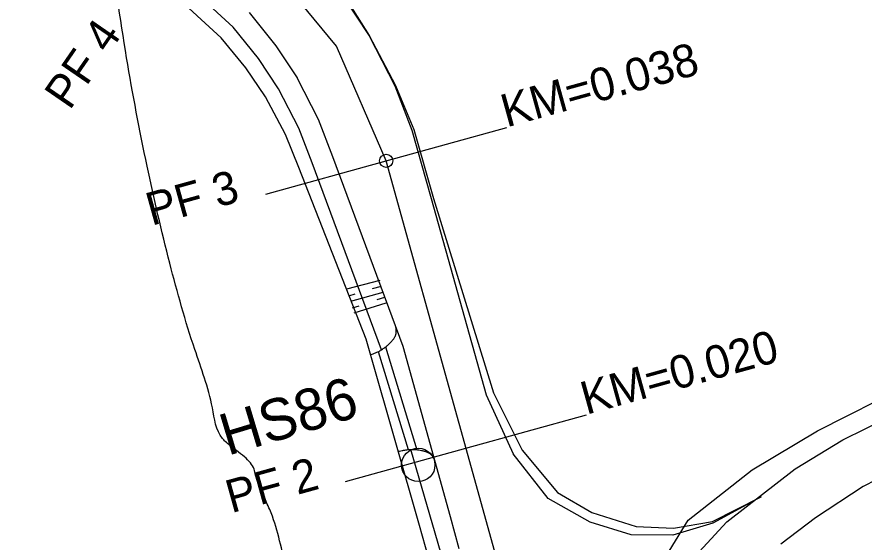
# Model space of a CAD drawing. Extents: x -478102 to -473059, y -1117705 to -1114104.
# Drawn here: x -476287.7 to -476236.8, y -1117086.7 to -1117055.2 of the extents above; entities that cross this region are included whole.
import ezdxf

# ---------------------------------------------------------------- set-up
doc = ezdxf.new("R2010")
doc.units = 0
for name, color, linetype in [('BodoveZnackySachtaKanalizacni', 7, 'Continuous'), ('cestn___p____kop', 7, 'Continuous'), ('cesty', 7, 'Continuous'), ('POLYGONY_SITUACE_PF', 7, 'Continuous'), ('POLYGONY_SITUACE_PF_POPISY', 7, 'Continuous'), ('POLYGONY_SITUACE_PO', 7, 'Continuous'), ('popis', 7, 'Continuous'), ('RozhraniKultur', 7, 'Continuous'), ('RozhraniVozovky', 7, 'Continuous'), ('TP_HS', 7, 'Continuous'), ('Vrstevnice_hlavni', 7, 'Continuous'), ('Vrstevnice_vedlejsi', 7, 'Continuous')]:
    doc.layers.add(name, color=color, linetype=linetype)

msp = doc.modelspace()

# ---------------------------------------------------------------- linework, layer by layer
at = {"layer": 'BodoveZnackySachtaKanalizacni'}
msp.add_circle((-476263.594, -1117082.052), 1, dxfattribs=at)
at = {"layer": 'cestn___p____kop'}
for p, q in [((-476265.9, -1117070.991), (-476267.895, -1117071.51)), ((-476265.814, -1117071.337), (-476266.354, -1117071.489)), ((-476267.765, -1117071.892), (-476267.384, -1117071.791)), ((-476265.713, -1117071.698), (-476267.664, -1117072.238)), ((-476265.533, -1117072.346), (-476267.456, -1117072.937)), ((-476265.626, -1117072.007), (-476266.087, -1117072.144)), ((-476267.549, -1117072.613), (-476267.146, -1117072.497))]:
    msp.add_line(p, q, dxfattribs=at)
at = {"layer": 'cesty'}
for p, q in [((-476274.708, -1117055.766), (-476277.732, -1117052.983)), ((-476268.093, -1117053.939), (-476266.552, -1117056.287)), ((-476268.033, -1117053.896), (-476266.535, -1117056.277)), ((-476273.752, -1117054.898), (-476272.135, -1117056.886)), ((-476273.179, -1117057.645), (-476274.708, -1117055.766)), ((-476266.552, -1117056.287), (-476265.008, -1117059.295)), ((-476266.535, -1117056.277), (-476264.959, -1117059.274)), ((-476272.135, -1117056.886), (-476270.863, -1117058.822)), ((-476271.976, -1117059.478), (-476273.179, -1117057.645)), ((-476269.578, -1117061.325), (-476270.863, -1117058.822)), ((-476270.762, -1117061.842), (-476271.976, -1117059.478)), ((-476268.718, -1117063.566), (-476269.578, -1117061.325)), ((-476269.962, -1117063.926), (-476270.762, -1117061.842)), ((-476264.504, -1117074.94), (-476268.718, -1117063.566)), ((-476265.802, -1117075.139), (-476269.962, -1117063.926)), ((-476262.821, -1117066.053), (-476259.518, -1117077.845)), ((-476262.685, -1117066.063), (-476259.083, -1117077.725)), ((-476261.667, -1117085.17), (-476264.504, -1117074.94)), ((-476259.518, -1117077.845), (-476257.901, -1117081.393)), ((-476259.083, -1117077.725), (-476257.353, -1117081.16)), ((-476258.59, -1117099.803), (-476264.043, -1117081.125)), ((-476255.801, -1117084.079), (-476257.901, -1117081.393)), ((-476257.353, -1117081.16), (-476255.233, -1117083.7)), ((-476255.233, -1117083.7), (-476253.179, -1117084.916)), ((-476245.946, -1117085.453), (-476243.022, -1117083.979)), ((-476243.022, -1117083.979), (-476245.917, -1117085.558)), ((-476243.022, -1117083.979), (-476243.022, -1117083.979)), ((-476253.277, -1117085.498), (-476255.801, -1117084.079)), ((-476253.179, -1117084.916), (-476250.53, -1117085.755)), ((-476261.133, -1117087.098), (-476261.667, -1117085.17)), ((-476250.826, -1117086.249), (-476253.277, -1117085.498)), ((-476253.277, -1117085.498), (-476253.277, -1117085.498)), ((-476245.917, -1117085.558), (-476248.318, -1117086.272)), ((-476248.281, -1117085.855), (-476245.946, -1117085.453)), ((-476250.53, -1117085.755), (-476248.281, -1117085.855)), ((-476248.318, -1117086.272), (-476250.826, -1117086.249))]:
    msp.add_line(p, q, dxfattribs=at)
for points in [[(-476266.732, -1117074.511), (-476270.768, -1117064.204), (-476271.566, -1117062.212), (-476272.761, -1117059.954), (-476273.936, -1117058.207), (-476275.415, -1117056.411), (-476278.317, -1117053.74), (-476280.366, -1117052.325), (-476282.34, -1117051.259), (-476283.992, -1117050.544), (-476285.595, -1117050.022), (-476288.167, -1117049.481), (-476290.873, -1117049.234), (-476293.603, -1117049.34), (-476293.603, -1117049.34), (-476299.076, -1117049.264)], [(-476265.008, -1117059.295), (-476263.985, -1117061.96), (-476262.821, -1117066.053)], [(-476264.959, -1117059.274), (-476263.868, -1117061.922), (-476262.685, -1117066.063)], [(-476266.45, -1117075.48), (-476266.732, -1117074.511)], [(-476263.521, -1117085.684), (-476266.45, -1117075.48)], [(-476262.981, -1117087.61), (-476263.521, -1117085.684)]]:
    msp.add_lwpolyline(points, dxfattribs=at)
at = {"layer": 'POLYGONY_SITUACE_PF'}
for points in [[(-476272.745, -1117065.801), (-476265.518, -1117063.797), (-476258.29, -1117061.793)], [(-476267.961, -1117083.054), (-476260.734, -1117081.05), (-476253.507, -1117079.047)]]:
    msp.add_lwpolyline(points, dxfattribs=at)
at = {"layer": 'POLYGONY_SITUACE_PO'}
msp.add_lwpolyline([(-476250.954, -1117100.054), (-476256.772, -1117095.342), (-476265.518, -1117063.797), (-476268.51, -1117056.912), (-476273.282, -1117051.116), (-476279.465, -1117046.859), (-476286.581, -1117044.469), (-476294.08, -1117044.131), (-476301.427, -1117045.065)], dxfattribs=at)
msp.add_circle((-476265.518, -1117063.797), 0.395, dxfattribs=at)
at = {"layer": 'RozhraniKultur'}
msp.add_lwpolyline([(-476326.155, -1117118.092), (-476289.536, -1117114.347), (-476268.698, -1117113.377), (-476254.616, -1117112.232), (-476253.368, -1117111.396), (-476254.26, -1117105.118), (-476253.444, -1117098.834), (-476252.052, -1117092.56), (-476249.674, -1117089.102), (-476247.41, -1117085.365), (-476243.552, -1117082.341), (-476239.642, -1117080.005), (-476234.251, -1117077.288), (-476223.428, -1117073.653), (-476215.212, -1117070.499), (-476211.753, -1117068.101), (-476207.257, -1117063.687), (-476203.922, -1117059.007), (-476201.245, -1117053.431), (-476199.908, -1117046.384), (-476198.206, -1117031.932)], dxfattribs=at)
at = {"layer": 'RozhraniVozovky'}
for points in [[(-476247.93, -1117088.545), (-476245.077, -1117085.472), (-476240.982, -1117082.296), (-476238.115, -1117080.557), (-476233.979, -1117078.501), (-476225.492, -1117075.329), (-476219.895, -1117073.227), (-476215.189, -1117071.158), (-476211.766, -1117069.21), (-476209.272, -1117067.263), (-476206.779, -1117064.716), (-476204.692, -1117061.981), (-476203, -1117058.967), (-476200.833, -1117053.375), (-476199.75, -1117048.873), (-476198.727, -1117040.3), (-476198.206, -1117031.932), (-476198.165, -1117024.787), (-476198.499, -1117019.299), (-476199.36, -1117013.806), (-476200.192, -1117009.793)], [(-476196.364, -1117012.13), (-476195.729, -1117017.189), (-476195.176, -1117023.395), (-476195.112, -1117027.233), (-476195.235, -1117031.513), (-476195.559, -1117037.637), (-476196.033, -1117043.394), (-476196.483, -1117047.979), (-476197.306, -1117052.252), (-476198.582, -1117056.674), (-476200.039, -1117060.081), (-476202.244, -1117063.965), (-476204.836, -1117067.407), (-476207.857, -1117070.218), (-476210.834, -1117072.302), (-476213.828, -1117073.953), (-476223.737, -1117077.95), (-476233.774, -1117081.756), (-476236.901, -1117083.35), (-476239.761, -1117085.24), (-476241.85, -1117086.802)]]:
    msp.add_lwpolyline(points, dxfattribs=at)
at = {"layer": 'TP_HS'}
for p, q in [((-476265.993, -1117075.246), (-476264.198, -1117081.134)), ((-476265.554, -1117074.971), (-476263.674, -1117081.139))]:
    msp.add_line(p, q, dxfattribs=at)
for points in [[(-476266.459, -1117075.447), (-476266.37, -1117075.412), (-476266.227, -1117075.352), (-476266.085, -1117075.289), (-476265.969, -1117075.234), (-476265.857, -1117075.172), (-476265.748, -1117075.106), (-476265.694, -1117075.07), (-476265.641, -1117075.034), (-476265.509, -1117074.935), (-476265.386, -1117074.827), (-476265.269, -1117074.711), (-476265.212, -1117074.65), (-476265.156, -1117074.588), (-476265.096, -1117074.517), (-476265.043, -1117074.443), (-476264.998, -1117074.365), (-476264.978, -1117074.323), (-476264.961, -1117074.279), (-476264.939, -1117074.212), (-476264.931, -1117074.177), (-476264.924, -1117074.142), (-476264.917, -1117074.074), (-476264.918, -1117074.005), (-476264.936, -1117073.778)], [(-476264.797, -1117081.237), (-476264.713, -1117081.218), (-476264.561, -1117081.188), (-476264.484, -1117081.174), (-476264.408, -1117081.161), (-476264.281, -1117081.142), (-476264.154, -1117081.131), (-476264.026, -1117081.125), (-476263.962, -1117081.124), (-476263.897, -1117081.124), (-476263.732, -1117081.133), (-476263.569, -1117081.154), (-476263.408, -1117081.185), (-476263.327, -1117081.203), (-476263.245, -1117081.224), (-476263.156, -1117081.249), (-476263.071, -1117081.281), (-476262.989, -1117081.321), (-476262.95, -1117081.344), (-476262.911, -1117081.371), (-476262.856, -1117081.415), (-476262.829, -1117081.439), (-476262.805, -1117081.464), (-476262.782, -1117081.49), (-476262.761, -1117081.517), (-476262.723, -1117081.575), (-476262.611, -1117081.773)]]:
    msp.add_spline(points, degree=3, dxfattribs=at)
at = {"layer": 'Vrstevnice_hlavni'}
msp.add_spline([(-476249.493, -1117108.392), (-476249.775, -1117107.699), (-476250.264, -1117106.97), (-476250.958, -1117106.207), (-476251.857, -1117105.408), (-476252.513, -1117105.14), (-476252.925, -1117105.402), (-476253.095, -1117106.195), (-476253.235, -1117107.1), (-476253.347, -1117108.118), (-476253.43, -1117109.248), (-476253.596, -1117109.985), (-476253.847, -1117110.328), (-476254.181, -1117110.278), (-476255.528, -1117110.336), (-476257.887, -1117110.502), (-476261.259, -1117110.776), (-476263.654, -1117110.928), (-476265.074, -1117110.957), (-476265.519, -1117110.863), (-476266.5, -1117108.002), (-476268.017, -1117102.375), (-476270.071, -1117093.98), (-476271.569, -1117088.098), (-476272.511, -1117084.73), (-476272.897, -1117083.874), (-476273.181, -1117083.184), (-476273.365, -1117082.66), (-476273.447, -1117082.301), (-476273.665, -1117081.937), (-476274.021, -1117081.569), (-476274.513, -1117081.196), (-476274.898, -1117080.887), (-476275.174, -1117080.644), (-476275.342, -1117080.466), (-476275.953, -1117078.624), (-476277.006, -1117075.118), (-476278.503, -1117069.948), (-476279.866, -1117064.113), (-476281.094, -1117057.612), (-476282.188, -1117050.447), (-476282.997, -1117045.306), (-476283.52, -1117042.188), (-476283.758, -1117041.094), (-476283.99, -1117040.218), (-476284.216, -1117039.561), (-476284.654, -1117038.684)], degree=3, dxfattribs=at)
at = {"layer": 'Vrstevnice_vedlejsi'}
for points in [[(-476361.641, -1116910.017), (-476360.991, -1116911.137), (-476360.552, -1116912.67), (-476360.323, -1116914.616), (-476360.306, -1116916.973), (-476360.308, -1116918.585), (-476360.329, -1116919.449), (-476360.369, -1116919.567), (-476360.386, -1116919.663), (-476360.38, -1116919.738), (-476360.35, -1116919.79), (-476360.486, -1116921.699), (-476360.787, -1116925.464), (-476361.254, -1116931.086), (-476361.67, -1116935.051), (-476362.037, -1116937.36), (-476362.353, -1116938.012), (-476362.549, -1116938.736), (-476362.623, -1116939.532), (-476362.576, -1116940.398), (-476362.264, -1116942.869), (-476361.686, -1116946.945), (-476360.843, -1116952.626), (-476360.093, -1116958.73), (-476359.435, -1116965.256), (-476358.871, -1116972.204), (-476358.36, -1116977.092), (-476357.904, -1116979.919), (-476357.501, -1116980.685), (-476356.57, -1116984.99), (-476355.11, -1116992.835), (-476353.122, -1117004.219), (-476351.571, -1117012.905), (-476350.455, -1117018.893), (-476349.776, -1117022.183), (-476349.504, -1117027.698), (-476349.639, -1117035.437), (-476350.182, -1117045.4), (-476350.307, -1117053.191), (-476350.012, -1117058.811), (-476349.298, -1117062.259), (-476350.091, -1117065.67), (-476352.39, -1117069.042), (-476356.195, -1117072.377), (-476359.92, -1117076.705), (-476363.566, -1117082.026), (-476367.131, -1117088.339), (-476371.33, -1117094.641), (-476376.164, -1117100.933), (-476381.631, -1117107.213), (-476386.474, -1117112.181), (-476390.692, -1117115.834), (-476394.286, -1117118.174), (-476397.491, -1117120.393), (-476400.306, -1117122.492), (-476402.732, -1117124.472), (-476402.928, -1117127.738), (-476400.894, -1117132.291), (-476396.631, -1117138.131), (-476389.647, -1117141.585), (-476379.944, -1117142.653), (-476367.521, -1117141.334), (-476355.525, -1117141.406), (-476343.957, -1117142.868), (-476332.816, -1117145.722), (-476324.482, -1117147.814), (-476318.952, -1117149.144), (-476316.229, -1117149.714), (-476310.745, -1117150.91), (-476302.502, -1117152.733), (-476291.498, -1117155.183), (-476284.107, -1117156.821), (-476280.33, -1117157.647), (-476280.165, -1117157.662), (-476279.816, -1117157.743), (-476279.284, -1117157.891), (-476278.569, -1117158.106), (-476278.072, -1117158.306), (-476277.796, -1117158.489), (-476277.739, -1117158.657), (-476277.684, -1117158.815), (-476277.629, -1117158.963), (-476277.576, -1117159.102), (-476277.523, -1117159.234), (-476277.472, -1117159.361), (-476277.423, -1117159.482), (-476277.379, -1117159.591), (-476277.34, -1117159.689), (-476277.307, -1117159.775), (-476277.275, -1117159.863), (-476277.243, -1117159.954), (-476277.212, -1117160.046), (-476277.173, -1117160.139), (-476277.129, -1117160.233), (-476277.078, -1117160.326), (-476277.04, -1117160.421), (-476277.015, -1117160.516)], [(-476223.981, -1117207.237), (-476224.285, -1117206.855), (-476224.501, -1117206.557), (-476224.628, -1117206.343), (-476224.668, -1117206.213), (-476224.801, -1117205.902), (-476225.026, -1117205.411), (-476225.345, -1117204.739), (-476225.578, -1117204.261), (-476225.727, -1117203.975), (-476225.791, -1117203.883), (-476225.875, -1117203.662), (-476225.98, -1117203.311), (-476226.105, -1117202.831), (-476226.229, -1117202.417), (-476226.352, -1117202.067), (-476226.475, -1117201.782), (-476226.572, -1117201.501), (-476226.643, -1117201.224), (-476226.689, -1117200.951), (-476227.057, -1117200.755), (-476227.747, -1117200.637), (-476228.759, -1117200.595), (-476229.446, -1117200.566), (-476229.808, -1117200.548), (-476229.845, -1117200.544), (-476229.875, -1117200.547), (-476229.898, -1117200.559), (-476229.914, -1117200.578), (-476229.923, -1117200.586), (-476229.927, -1117200.583), (-476229.925, -1117200.567), (-476229.926, -1117200.55), (-476229.93, -1117200.533), (-476229.937, -1117200.515), (-476230.309, -1117199.985), (-476231.045, -1117198.942), (-476232.146, -1117197.387), (-476233.138, -1117195.885), (-476234.022, -1117194.438), (-476234.797, -1117193.044), (-476236.35, -1117190.18), (-476238.683, -1117185.847), (-476241.794, -1117180.043), (-476244.171, -1117175.438), (-476245.814, -1117172.033), (-476246.723, -1117169.826), (-476247.372, -1117168.01), (-476247.761, -1117166.585), (-476247.891, -1117165.55), (-476248.161, -1117164.525), (-476248.57, -1117163.508), (-476249.119, -1117162.501), (-476249.598, -1117161.498), (-476250.007, -1117160.498), (-476250.346, -1117159.503), (-476250.69, -1117158.53), (-476251.038, -1117157.58), (-476251.39, -1117156.652), (-476251.803, -1117155.599), (-476252.277, -1117154.423), (-476252.812, -1117153.123), (-476253.36, -1117151.76), (-476253.922, -1117150.336), (-476254.497, -1117148.85), (-476255.085, -1117147.257), (-476255.684, -1117145.558), (-476256.294, -1117143.752), (-476259.267, -1117141.777), (-476264.603, -1117139.631), (-476272.302, -1117137.316), (-476278.025, -1117135.721), (-476281.773, -1117134.847), (-476283.545, -1117134.694), (-476286.438, -1117134.211), (-476290.451, -1117133.398), (-476295.585, -1117132.255), (-476301.704, -1117130.929), (-476308.808, -1117129.42), (-476316.898, -1117127.729), (-476324.767, -1117125.966), (-476332.416, -1117124.134), (-476339.844, -1117122.232), (-476344.627, -1117120.838), (-476346.763, -1117119.952), (-476346.254, -1117119.574), (-476345.231, -1117118.402), (-476343.693, -1117116.434), (-476341.642, -1117113.672), (-476338.379, -1117110.142), (-476333.906, -1117105.844), (-476328.223, -1117100.779), (-476323.405, -1117096.497), (-476319.453, -1117093.001), (-476316.366, -1117090.289), (-476314.122, -1117087.639), (-476312.721, -1117085.051)]]:
    msp.add_spline(points, degree=3, dxfattribs=at)

# ---------------------------------------------------------------- texts
at = {"layer": 'POLYGONY_SITUACE_PF_POPISY'}
for s, rotation, p in [('PF 4', 55.4518, (-476284.513, -1117060.81)), ('KM=0.038', 15.4963, (-476258.302, -1117061.796)), ('PF 3', 15.4963, (-476279.602, -1117067.702)), ('KM=0.020', 15.4963, (-476253.518, -1117079.05)), ('PF 2', 15.4963, (-476274.818, -1117084.955))]:
    msp.add_text(s, height=1.9765, rotation=rotation, dxfattribs=at).set_placement(p)
at = {"layer": 'popis'}
msp.add_text('HS86', height=2.5, rotation=16.7821, dxfattribs=at).set_placement((-476275.034, -1117081.512))

doc.saveas('drawing.dxf')
